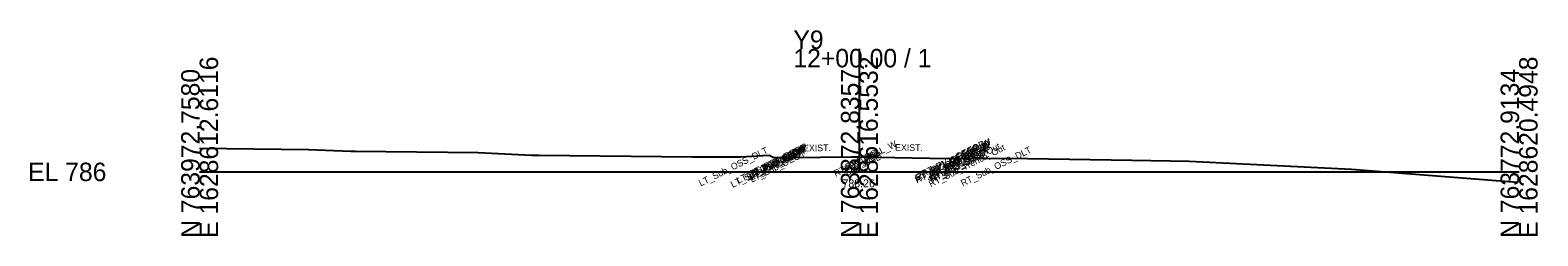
# Model space of a CAD drawing. Extents: x -26 to 203, y -10 to 6017.
# Drawn here: x -25.7 to 202.8, y 3990.3 to 4021.5 of the extents above; entities that cross this region are included whole.
import ezdxf

# ---------------------------------------------------------------- set-up
doc = ezdxf.new("R2010")
doc.units = 0
for name, color, linetype in [('Default', 7, 'Continuous'), ('Exist Cross Section Cell', 7, 'Continuous'), ('Exist XS Center Line Elevation Label', 7, 'Continuous'), ('Exist XS Ground Line', 7, 'Continuous'), ('Prop XS SE Text', 7, 'Continuous'), ('Scratch_Level_0', 7, 'Continuous')]:
    doc.layers.add(name, color=color, linetype=linetype)

msp = doc.modelspace()

# ---------------------------------------------------------------- linework, layer by layer
at = {"layer": 'Exist Cross Section Cell'}
for p, q in [((100, 4000), (100, 4018.64)), ((0, 4000), (100, 4000)), ((100, 4000), (200, 4000))]:
    msp.add_line(p, q, dxfattribs=at)
at = {"layer": 'Exist XS Ground Line'}
msp.add_lwpolyline([(0, 4003.61), (16.52, 4003.37), (22.89, 4003.13), (23.59, 4003.15), (42.2, 4002.95), (50.32, 4002.54), (51.42, 4002.52), (74.68, 4002.26), (81.58, 4002.29), (81.97, 4002.3), (86.32, 4002.53), (87.02, 4002.16), (89.45, 4002.19), (98.81, 4002.28), (100, 4002.26), (113.37, 4002.04), (114.32, 4002.06), (125.51, 4002.02), (141.28, 4001.76), (149.99, 4001.62), (174.58, 4000.42), (199.74, 3998.46)], dxfattribs=at)

# ---------------------------------------------------------------- texts
at = {"layer": 'Default'}
msp.add_text('-', height=0.0001, dxfattribs=at).set_placement((0, 4000))
at = {"layer": 'Exist Cross Section Cell'}
for s, p in [('Y9', (90, 4018.64)), ('12+00.00 / 1', (90, 4015.84)), ('EL 786', (-26, 3998.6))]:
    msp.add_text(s, height=2.8, dxfattribs=at).set_placement(p)
for s, p in [('N 763972.7580', (0, 3990)), ('E 1628612.6116', (2.8, 3990)), ('N 763872.8357', (100, 3990)), ('E 1628616.5532', (102.8, 3990)), ('N 763772.9134', (200, 3990)), ('E 1628620.4948', (202.8, 3990))]:
    msp.add_text(s, height=2.8, rotation=90, dxfattribs=at).set_placement(p)
at = {"layer": 'Exist XS Center Line Elevation Label'}
msp.add_text('788.26', height=1.2, dxfattribs=at).set_placement((97.44, 3997.66))
at = {"layer": 'Prop XS SE Text'}
for rotation, p in [(1.1458, (91.47, 4003.09)), (359.4271, (105.4, 4003.21))]:
    msp.add_text('EXIST.', height=1, rotation=rotation, dxfattribs=at).set_placement(p)
at = {"layer": 'Scratch_Level_0'}
for s, p in [('LT_Sub_Trench_Out', (80.8, 3997.57)), ('LT_PS3_Shelf_Out', (81.68, 3998.2)), ('LT_PS2_OEOP', (83.44, 3998.97)), ('LT_PV2_OEOT', (83.66, 3998.95)), ('LT_PV1_OEOT', (83.77, 3999.26)), ('LT_PS1_OEOP', (83.8, 3999.28)), ('RT_PV1_PGL_W', (96.41, 3999.22)), ('RT_PV2_OEEOP_W', (108.73, 3998.47)), ('RT_PV3_OEEOP_W', (108.73, 3998.22)), ('RT_PV1_OEEOP_W', (108.84, 3998.65)), ('RT_PV1_OEEOP', (109.7, 3999.2)), ('RT_Sub_Trench_Out', (110.83, 3997.66)), ('RT_PV2_OEOT', (110.9, 3999.04)), ('RT_PV3_OEOT', (110.9, 3998.79)), ('RT_PS3_Shelf_Out', (110.94, 3998.29)), ('RT_PV1_OEOT', (111.01, 3999.35)), ('RT_PS1_OEOP', (111.05, 3999.37)), ('RT_PS2_OEOP', (111.2, 3999.06)), ('RT_PS3_OEOP', (111.45, 3998.8)), ('RT_Sub_OSS_DLT', (115.68, 3997.76)), ('LT_Sub_OSS_DLT', (75.95, 3997.79)), ('LT_PS3_OEOP', (83.19, 3998.71)), ('LT_PV3_OEOT', (83.66, 3998.7)), ('LT_Sub_OEOT', (83.68, 3998.34)), ('PV2_PGL', (98.08, 3999.93)), ('PV3_PGL', (98.08, 3999.68)), ('Sub_PGL', (98.1, 3999.32)), ('PV1_PGL', (98.18, 4000.23)), ('RT_Sub_OEOT', (110.93, 3998.43))]:
    msp.add_text(s, height=1, rotation=26.5651, dxfattribs=at).set_placement(p)

doc.saveas('drawing.dxf')
